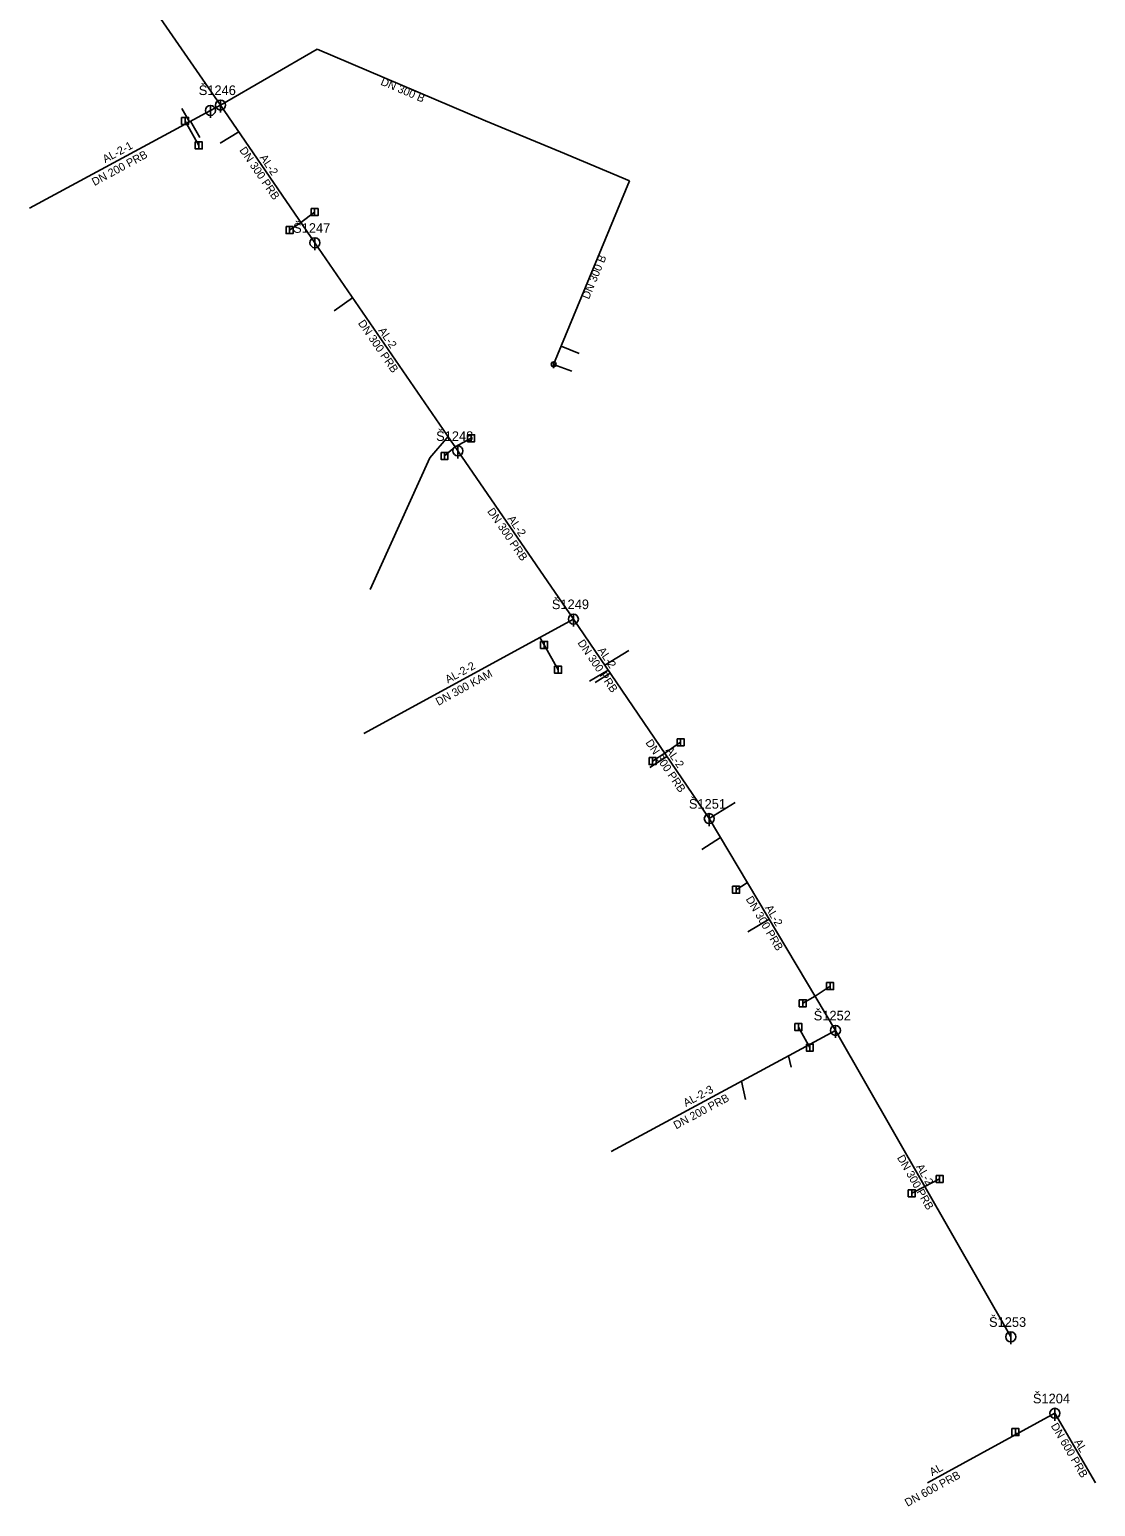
# Model space of a CAD drawing. Extents: x -482852 to -482359, y -1127974 to -1127429.
# Drawn here: x -482572.2 to -482358.5, y -1127974 to -1127677.8 of the extents above; entities that cross this region are included whole.
import ezdxf

# ---------------------------------------------------------------- set-up
doc = ezdxf.new("R2010")
doc.units = 0
for name, color, linetype in [('_pripojka_kanal_destova_priblizne_', 7, 'Continuous'), ('_pripojka_kanal_jednotna_priblizne_', 7, 'Continuous'), ('_pripojka_kanal_splaskova_priblizne_', 7, 'Continuous'), ('_stoka_jednotna_smvak_prevzato_z_dokumentace_', 7, 'Continuous'), ('Default', 7, 'Continuous'), ('MoLevel 119', 7, 'Continuous'), ('MoLevel 120', 7, 'Continuous'), ('MoLevel 57', 7, 'Continuous'), ('MoLevel 60', 7, 'Continuous'), ('MoLevel 63', 7, 'Continuous'), ('MoLevel 68', 7, 'Continuous'), ('MoLevel 69', 7, 'Continuous')]:
    doc.layers.add(name, color=color, linetype=linetype)

# ---------------------------------------------------------------- blocks, each defined once
blk = doc.blocks.new('_vpust_')
at = {"layer": 'Default'}
blk.add_line((0, 0.000025), (0, -0.000025), dxfattribs=at)
blk.add_lwpolyline([(-0.000035, 0.000035), (0.000035, 0.000035), (0.000035, -0.000035), (-0.000035, -0.000035), (-0.000035, 0.000035)], dxfattribs=at)
blk = doc.blocks.new('_sachta_kanal_prip_')
at = {"layer": 'Default'}
blk.add_line((0, 0.00005), (0, -0.000075), dxfattribs=at)
blk.add_circle((0, 0), 0.00005, dxfattribs=at)
blk = doc.blocks.new('_sachta_kanal_prevzato_z_dokumentace_')
at = {"layer": 'Default'}
blk.add_line((0, 0.00005), (0, -0.000075), dxfattribs=at)
blk.add_circle((0, 0), 0.00005, dxfattribs=at)

msp = doc.modelspace()

# ---------------------------------------------------------------- linework, layer by layer
at = {"layer": '_pripojka_kanal_destova_priblizne_'}
for p, q in [((-482541.01, -1127696.13), (-482540.75, -1127696.61)), ((-482538.28, -1127701.04), (-482540.75, -1127696.61)), ((-482515.05, -1127714.41), (-482517.78, -1127716.5)), ((-482520.06, -1127718), (-482517.78, -1127716.5)), ((-482489.01, -1127763.31), (-482486.88, -1127761.49)), ((-482483.69, -1127759.76), (-482486.88, -1127761.49)), ((-482469.04, -1127801.2), (-482469.89, -1127799.7)), ((-482466.23, -1127806.18), (-482469.04, -1127801.2)), ((-482441.67, -1127820.73), (-482444.86, -1127822.93)), ((-482447.29, -1127824.51), (-482444.86, -1127822.93)), ((-482430.55, -1127850.3), (-482428.29, -1127848.87)), ((-482417.2, -1127873.08), (-482414.73, -1127871.63)), ((-482411.71, -1127869.62), (-482414.73, -1127871.63)), ((-482418.07, -1127877.86), (-482416.06, -1127881.45)), ((-482415.77, -1127881.96), (-482416.06, -1127881.45)), ((-482395.34, -1127911.19), (-482392.74, -1127909.8)), ((-482389.76, -1127908.31), (-482392.74, -1127909.8)), ((-482374.55, -1127959.08), (-482374.31, -1127959.49))]:
    msp.add_line(p, q, dxfattribs=at)
msp.add_lwpolyline([(-482503.91, -1127790.1), (-482491.96, -1127763.66), (-482488.3, -1127759.42)], dxfattribs=at)
at = {"layer": '_pripojka_kanal_jednotna_priblizne_'}
for p, q in [((-482541.68, -1127693.62), (-482540.12, -1127696.28)), ((-482538.08, -1127699.41), (-482539.9, -1127696.16)), ((-482533.97, -1127700.6), (-482530.25, -1127698.3)), ((-482511.11, -1127734.18), (-482507.43, -1127731.57)), ((-482452.04, -1127802.31), (-482456.86, -1127805.3)), ((-482459.94, -1127808.45), (-482456.19, -1127806.3)), ((-482458.78, -1127808.76), (-482455.8, -1127806.86)), ((-482447.82, -1127825.78), (-482444.43, -1127823.56)), ((-482430.73, -1127832.84), (-482435.93, -1127836.05)), ((-482437.42, -1127842.22), (-482433.66, -1127839.86)), ((-482428.18, -1127858.77), (-482423.93, -1127856.18)), ((-482419.51, -1127885.87), (-482420.07, -1127883.61)), ((-482428.68, -1127892.35), (-482429.45, -1127888.68))]:
    msp.add_line(p, q, dxfattribs=at)
at = {"layer": '_pripojka_kanal_splaskova_priblizne_'}
for p, q in [((-482514.57, -1127681.7), (-482533.92, -1127692.93)), ((-482467.13, -1127744.94), (-482451.94, -1127708.13)), ((-482462.01, -1127742.75), (-482465.62, -1127741.26)), ((-482463.5, -1127746.3), (-482467.13, -1127744.94))]:
    msp.add_line(p, q, dxfattribs=at)
msp.add_lwpolyline([(-482451.94, -1127708.13), (-482465.74, -1127702.32), (-482480.82, -1127696.07), (-482514.57, -1127681.7)], dxfattribs=at)
at = {"layer": '_stoka_jednotna_smvak_prevzato_z_dokumentace_'}
for p, q in [((-482533.92, -1127692.93), (-482567.4, -1127644.54)), ((-482572.2, -1127713.59), (-482535.93, -1127694.01)), ((-482535.93, -1127694.01), (-482533.92, -1127692.93)), ((-482515, -1127720.56), (-482533.92, -1127692.93)), ((-482486.33, -1127762.3), (-482515, -1127720.56)), ((-482463.17, -1127796.03), (-482486.33, -1127762.3)), ((-482505.17, -1127818.97), (-482463.17, -1127796.03)), ((-482450.18, -1127815.11), (-482463.17, -1127796.03)), ((-482435.93, -1127836.05), (-482450.18, -1127815.11)), ((-482410.63, -1127878.51), (-482435.93, -1127836.05)), ((-482455.59, -1127902.79), (-482410.63, -1127878.51)), ((-482375.49, -1127939.97), (-482410.63, -1127878.51)), ((-482366.64, -1127955.31), (-482392.15, -1127969.23)), ((-482358.51, -1127969.23), (-482366.64, -1127955.31))]:
    msp.add_line(p, q, dxfattribs=at)

# ---------------------------------------------------------------- block references
at = {"layer": 'MoLevel 119', "xscale": 20000, "yscale": 20000}
for p in [(-482535.93, -1127694.01), (-482533.92, -1127692.93), (-482515, -1127720.56), (-482486.33, -1127762.3), (-482463.17, -1127796.03), (-482435.93, -1127836.05), (-482410.63, -1127878.51), (-482375.49, -1127939.97), (-482366.64, -1127955.31)]:
    msp.add_blockref('_sachta_kanal_prevzato_z_dokumentace_', p, dxfattribs=at)
at = {"layer": 'MoLevel 57', "xscale": 10000, "yscale": 10000}
msp.add_blockref('_sachta_kanal_prip_', (-482467.13, -1127744.94), dxfattribs=at)
at = {"layer": 'MoLevel 63', "xscale": 20000, "yscale": 20000}
for p in [(-482541.01, -1127696.13), (-482538.28, -1127701.04), (-482515.05, -1127714.41), (-482520.06, -1127718), (-482483.69, -1127759.76), (-482489.01, -1127763.31), (-482469.04, -1127801.2), (-482466.23, -1127806.18), (-482441.67, -1127820.73), (-482447.29, -1127824.51), (-482430.55, -1127850.3), (-482411.71, -1127869.62), (-482417.2, -1127873.08), (-482418.07, -1127877.86), (-482415.77, -1127881.96), (-482389.76, -1127908.31), (-482395.34, -1127911.19), (-482374.55, -1127959.08)]:
    msp.add_blockref('_vpust_', p, dxfattribs=at)

# ---------------------------------------------------------------- texts
at = {"layer": 'MoLevel 120'}
for s, p in [('Š1246', (-482538.28, -1127690.93)), ('Š1247', (-482519.36, -1127718.56)), ('Š1248', (-482490.69, -1127760.3)), ('Š1249', (-482467.49, -1127794.03)), ('Š1251', (-482440.02, -1127834.05)), ('Š1252', (-482414.99, -1127876.51)), ('Š1253', (-482379.85, -1127937.97)), ('Š1204', (-482371.05, -1127953.31))]:
    msp.add_text(s, height=1.926, dxfattribs=at).set_placement(p)
at = {"layer": 'MoLevel 60'}
for rotation, p in [(336.9315, (-482501.95, -1127688.82)), (67.574, (-482460.06, -1127732.01))]:
    msp.add_text('DN 300 B', height=1.605, rotation=rotation, dxfattribs=at).set_placement(p)
at = {"layer": 'MoLevel 68'}
for s, rotation, p in [('DN 200 PRB', 28.3561, (-482559.19, -1127709.19)), ('DN 300 PRB', 304.4019, (-482530.21, -1127701.99)), ('DN 300 PRB', 304.4873, (-482506.42, -1127736.68)), ('DN 300 PRB', 304.4625, (-482480.51, -1127774.41)), ('DN 300 PRB', 304.2484, (-482462.41, -1127800.8)), ('DN 300 KAM', 28.6427, (-482490.24, -1127813.45)), ('DN 300 PRB', 304.2474, (-482448.79, -1127820.81)), ('DN 300 PRB', 300.7885, (-482428.67, -1127852.17)), ('DN 200 PRB', 28.3662, (-482442.57, -1127898.38)), ('DN 300 PRB', 299.7593, (-482398.34, -1127904.04)), ('DN 600 PRB', 300.2876, (-482367.51, -1127957.81)), ('DN 600 PRB', 28.6342, (-482396.2, -1127974.08))]:
    msp.add_text(s, height=1.605, rotation=rotation, dxfattribs=at).set_placement(p)
at = {"layer": 'MoLevel 69'}
for s, rotation, p in [('AL-2-1', 28.3561, (-482557.03, -1127704.6)), ('AL-2', 304.4019, (-482526.14, -1127703.49)), ('AL-2', 304.4873, (-482502.35, -1127738.17)), ('AL-2', 304.4625, (-482476.44, -1127775.91)), ('AL-2', 304.2484, (-482458.36, -1127802.31)), ('AL-2-2', 28.6427, (-482488.33, -1127808.97)), ('AL-2', 304.2474, (-482444.74, -1127822.32)), ('AL-2', 300.7885, (-482424.81, -1127853.92)), ('AL-2-3', 28.3662, (-482440.61, -1127893.9)), ('AL-2', 299.7593, (-482394.54, -1127905.85)), ('AL', 300.2876, (-482362.83, -1127961.04)), ('AL', 28.6342, (-482391.24, -1127967.94))]:
    msp.add_text(s, height=1.605, rotation=rotation, dxfattribs=at).set_placement(p)

doc.saveas('drawing.dxf')
